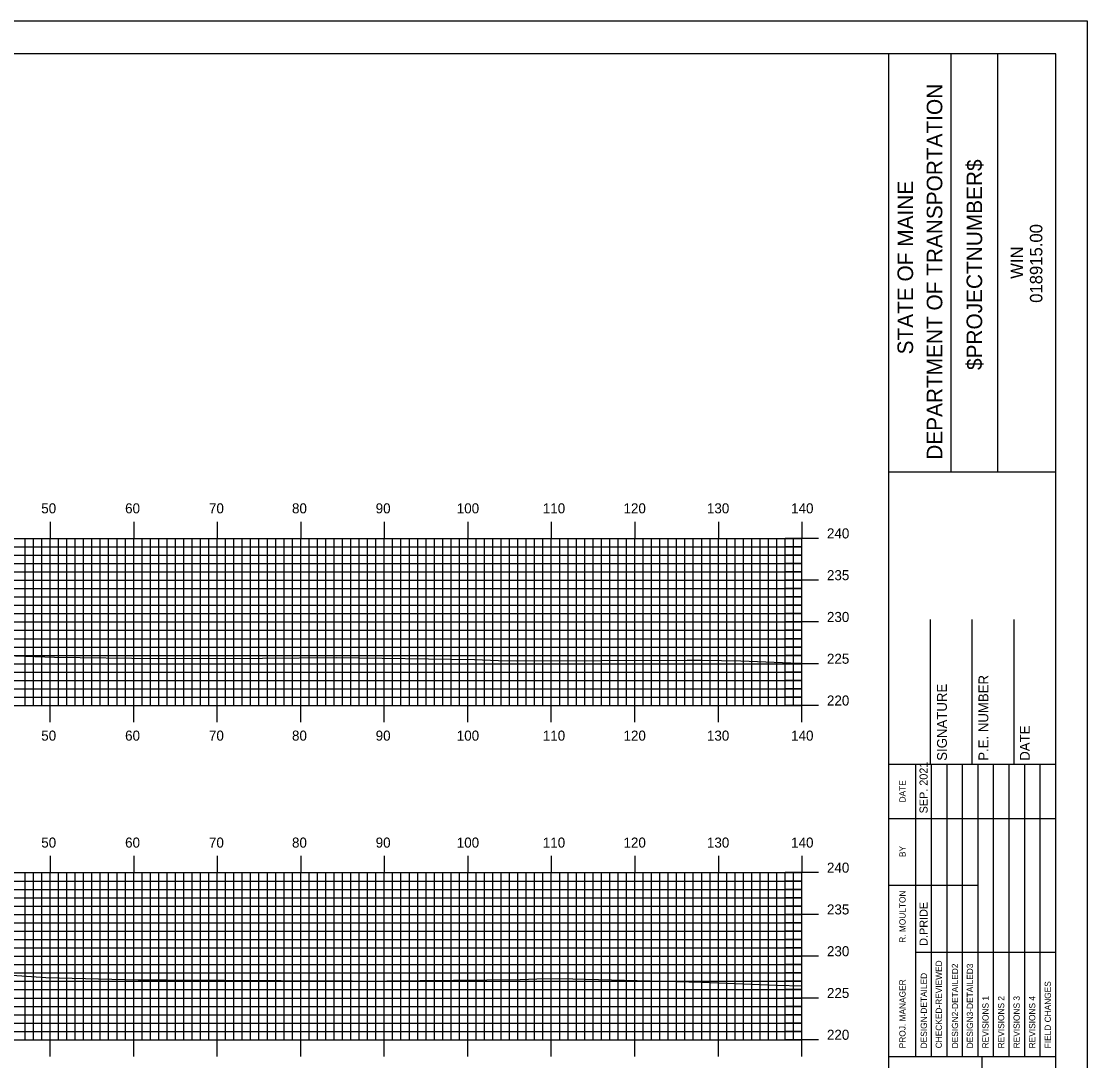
# Model space of a CAD drawing. Extents: x 1803503 to 1803847, y 442591 to 442811.
# Drawn here: x 1803715.7 to 1803843.4, y 442686.2 to 442810.5 of the extents above; entities that cross this region are included whole.
import ezdxf

# ---------------------------------------------------------------- set-up
doc = ezdxf.new("R2010")
doc.units = 0
for name, color, linetype in [('BORDER', 7, 'Continuous'), ('H_V ANNOTATION', 7, 'Continuous'), ('MAJOR', 7, 'Continuous'), ('MINOR', 7, 'Continuous'), ('PLOT BOUNDARY', 7, 'Continuous'), ('S_Roadway_Centerline', 7, 'Continuous')]:
    doc.layers.add(name, color=color, linetype=linetype)

msp = doc.modelspace()

# ---------------------------------------------------------------- linework, layer by layer
at = {"layer": 'BORDER'}
for p, q in [((1803819.54, 442596.67), (1803819.54, 442806.67)), ((1803827, 442756.66), (1803827, 442806.66)), ((1803832.59, 442756.66), (1803832.59, 442806.66)), ((1803819.54, 442756.65), (1803839.54, 442756.65)), ((1803824.54, 442721.67), (1803824.54, 442738.97)), ((1803829.54, 442721.67), (1803829.54, 442738.97)), ((1803834.54, 442721.67), (1803834.54, 442738.97)), ((1803819.54, 442721.67), (1803839.54, 442721.67)), ((1803819.54, 442686.67), (1803839.54, 442686.67)), ((1803830.72, 442616.67), (1803830.72, 442686.67))]:
    msp.add_line(p, q, dxfattribs=at)
msp.add_lwpolyline([(1803519.54, 442596.67), (1803839.54, 442596.67), (1803839.54, 442806.67), (1803519.54, 442806.67)], close=True, dxfattribs=at)
for points in [[(1803822.77, 442715.17), (1803822.77, 442721.67)], [(1803824.64, 442686.68), (1803824.64, 442721.67)], [(1803826.5, 442721.67), (1803826.5, 442686.68)], [(1803828.36, 442686.68), (1803828.36, 442721.67)], [(1803830.23, 442686.68), (1803830.23, 442721.67)], [(1803832.09, 442686.68), (1803832.09, 442721.67)], [(1803833.95, 442686.68), (1803833.95, 442721.67)], [(1803835.82, 442686.68), (1803835.82, 442721.67)], [(1803837.68, 442686.68), (1803837.68, 442721.67)], [(1803822.77, 442686.68), (1803822.77, 442720.26)], [(1803819.54, 442715.17), (1803839.54, 442715.17)], [(1803819.54, 442707.17), (1803822.77, 442707.17)], [(1803822.77, 442707.17), (1803830.22, 442707.17)], [(1803822.77, 442699.17), (1803839.54, 442699.17)]]:
    msp.add_lwpolyline(points, dxfattribs=at)
at = {"layer": 'MAJOR'}
for p, q in [((1803719.14, 442750.67), (1803719.14, 442748.67)), ((1803729.14, 442750.67), (1803729.14, 442748.67)), ((1803739.14, 442750.67), (1803739.14, 442748.67)), ((1803749.14, 442750.67), (1803749.14, 442748.67)), ((1803759.14, 442750.67), (1803759.14, 442748.67)), ((1803769.14, 442750.67), (1803769.14, 442748.67)), ((1803779.14, 442750.67), (1803779.14, 442748.67)), ((1803789.14, 442750.67), (1803789.14, 442748.67)), ((1803799.14, 442750.67), (1803799.14, 442748.67)), ((1803809.14, 442750.67), (1803809.14, 442748.67)), ((1803529.14, 442748.67), (1803809.14, 442748.67)), ((1803529.14, 442748.67), (1803809.14, 442748.67)), ((1803719.14, 442728.67), (1803719.14, 442748.67)), ((1803729.14, 442728.67), (1803729.14, 442748.67)), ((1803739.14, 442728.67), (1803739.14, 442748.67)), ((1803749.14, 442728.67), (1803749.14, 442748.67)), ((1803759.14, 442728.67), (1803759.14, 442748.67)), ((1803769.14, 442728.67), (1803769.14, 442748.67)), ((1803779.14, 442728.67), (1803779.14, 442748.67)), ((1803789.14, 442728.67), (1803789.14, 442748.67)), ((1803799.14, 442728.67), (1803799.14, 442748.67)), ((1803811.14, 442748.67), (1803807.14, 442748.67)), ((1803809.14, 442728.67), (1803809.14, 442748.67)), ((1803809.14, 442728.67), (1803809.14, 442748.67)), ((1803529.14, 442743.67), (1803809.14, 442743.67)), ((1803811.14, 442743.67), (1803807.14, 442743.67)), ((1803529.14, 442738.67), (1803809.14, 442738.67)), ((1803811.14, 442738.67), (1803807.14, 442738.67)), ((1803529.14, 442733.67), (1803809.14, 442733.67)), ((1803811.14, 442733.67), (1803807.14, 442733.67)), ((1803529.14, 442728.67), (1803809.14, 442728.67)), ((1803529.14, 442728.67), (1803809.14, 442728.67)), ((1803719.14, 442726.66), (1803719.14, 442728.67)), ((1803729.14, 442726.66), (1803729.14, 442728.67)), ((1803739.14, 442726.66), (1803739.14, 442728.67)), ((1803749.14, 442726.66), (1803749.14, 442728.67)), ((1803759.14, 442726.66), (1803759.14, 442728.67)), ((1803769.14, 442726.66), (1803769.14, 442728.67)), ((1803779.14, 442726.66), (1803779.14, 442728.67)), ((1803789.14, 442726.66), (1803789.14, 442728.67)), ((1803799.14, 442726.66), (1803799.14, 442728.67)), ((1803811.14, 442728.67), (1803807.14, 442728.67)), ((1803809.14, 442726.66), (1803809.14, 442728.67)), ((1803719.14, 442710.67), (1803719.14, 442708.67)), ((1803729.14, 442710.67), (1803729.14, 442708.67)), ((1803739.14, 442710.67), (1803739.14, 442708.67)), ((1803749.14, 442710.67), (1803749.14, 442708.67)), ((1803759.14, 442710.67), (1803759.14, 442708.67)), ((1803769.14, 442710.67), (1803769.14, 442708.67)), ((1803779.14, 442710.67), (1803779.14, 442708.67)), ((1803789.14, 442710.67), (1803789.14, 442708.67)), ((1803799.14, 442710.67), (1803799.14, 442708.67)), ((1803809.14, 442710.67), (1803809.14, 442708.67)), ((1803529.14, 442708.67), (1803809.14, 442708.67)), ((1803529.14, 442708.67), (1803809.14, 442708.67)), ((1803719.14, 442688.67), (1803719.14, 442708.67)), ((1803729.14, 442688.67), (1803729.14, 442708.67)), ((1803739.14, 442688.67), (1803739.14, 442708.67)), ((1803749.14, 442688.67), (1803749.14, 442708.67)), ((1803759.14, 442688.67), (1803759.14, 442708.67)), ((1803769.14, 442688.67), (1803769.14, 442708.67)), ((1803779.14, 442688.67), (1803779.14, 442708.67)), ((1803789.14, 442688.67), (1803789.14, 442708.67)), ((1803799.14, 442688.67), (1803799.14, 442708.67)), ((1803811.14, 442708.67), (1803807.14, 442708.67)), ((1803809.14, 442688.67), (1803809.14, 442708.67)), ((1803809.14, 442688.67), (1803809.14, 442708.67)), ((1803529.14, 442703.67), (1803809.14, 442703.67)), ((1803811.14, 442703.67), (1803807.14, 442703.67)), ((1803529.14, 442698.67), (1803809.14, 442698.67)), ((1803811.14, 442698.67), (1803807.14, 442698.67)), ((1803529.14, 442693.67), (1803809.14, 442693.67)), ((1803811.14, 442693.67), (1803807.14, 442693.67)), ((1803529.14, 442688.67), (1803809.14, 442688.67)), ((1803529.14, 442688.67), (1803809.14, 442688.67)), ((1803719.14, 442686.66), (1803719.14, 442688.67)), ((1803729.14, 442686.66), (1803729.14, 442688.67)), ((1803739.14, 442686.66), (1803739.14, 442688.67)), ((1803749.14, 442686.66), (1803749.14, 442688.67)), ((1803759.14, 442686.66), (1803759.14, 442688.67)), ((1803769.14, 442686.66), (1803769.14, 442688.67)), ((1803779.14, 442686.66), (1803779.14, 442688.67)), ((1803789.14, 442686.66), (1803789.14, 442688.67)), ((1803799.14, 442686.66), (1803799.14, 442688.67)), ((1803811.14, 442688.67), (1803807.14, 442688.67)), ((1803809.14, 442686.66), (1803809.14, 442688.67))]:
    msp.add_line(p, q, dxfattribs=at)
at = {"layer": 'MINOR'}
for p, q in [((1803716.14, 442728.67), (1803716.14, 442748.67)), ((1803717.14, 442728.67), (1803717.14, 442748.67)), ((1803718.14, 442728.67), (1803718.14, 442748.67)), ((1803720.14, 442728.67), (1803720.14, 442748.67)), ((1803721.14, 442728.67), (1803721.14, 442748.67)), ((1803722.14, 442728.67), (1803722.14, 442748.67)), ((1803723.14, 442728.67), (1803723.14, 442748.67)), ((1803724.14, 442728.67), (1803724.14, 442748.67)), ((1803725.14, 442728.67), (1803725.14, 442748.67)), ((1803726.14, 442728.67), (1803726.14, 442748.67)), ((1803727.14, 442728.67), (1803727.14, 442748.67)), ((1803728.14, 442728.67), (1803728.14, 442748.67)), ((1803730.14, 442728.67), (1803730.14, 442748.67)), ((1803731.14, 442728.67), (1803731.14, 442748.67)), ((1803732.14, 442728.67), (1803732.14, 442748.67)), ((1803733.14, 442728.67), (1803733.14, 442748.67)), ((1803734.14, 442728.67), (1803734.14, 442748.67)), ((1803735.14, 442728.67), (1803735.14, 442748.67)), ((1803736.14, 442728.67), (1803736.14, 442748.67)), ((1803737.14, 442728.67), (1803737.14, 442748.67)), ((1803738.14, 442728.67), (1803738.14, 442748.67)), ((1803740.14, 442728.67), (1803740.14, 442748.67)), ((1803741.14, 442728.67), (1803741.14, 442748.67)), ((1803742.14, 442728.67), (1803742.14, 442748.67)), ((1803743.14, 442728.67), (1803743.14, 442748.67)), ((1803744.14, 442728.67), (1803744.14, 442748.67)), ((1803745.14, 442728.67), (1803745.14, 442748.67)), ((1803746.14, 442728.67), (1803746.14, 442748.67)), ((1803747.14, 442728.67), (1803747.14, 442748.67)), ((1803748.14, 442728.67), (1803748.14, 442748.67)), ((1803750.14, 442728.67), (1803750.14, 442748.67)), ((1803751.14, 442728.67), (1803751.14, 442748.67)), ((1803752.14, 442728.67), (1803752.14, 442748.67)), ((1803753.14, 442728.67), (1803753.14, 442748.67)), ((1803754.14, 442728.67), (1803754.14, 442748.67)), ((1803755.14, 442728.67), (1803755.14, 442748.67)), ((1803756.14, 442728.67), (1803756.14, 442748.67)), ((1803757.14, 442728.67), (1803757.14, 442748.67)), ((1803758.14, 442728.67), (1803758.14, 442748.67)), ((1803760.14, 442728.67), (1803760.14, 442748.67)), ((1803761.14, 442728.67), (1803761.14, 442748.67)), ((1803762.14, 442728.67), (1803762.14, 442748.67)), ((1803763.14, 442728.67), (1803763.14, 442748.67)), ((1803764.14, 442728.67), (1803764.14, 442748.67)), ((1803765.14, 442728.67), (1803765.14, 442748.67)), ((1803766.14, 442728.67), (1803766.14, 442748.67)), ((1803767.14, 442728.67), (1803767.14, 442748.67)), ((1803768.14, 442728.67), (1803768.14, 442748.67)), ((1803770.14, 442728.67), (1803770.14, 442748.67)), ((1803771.14, 442728.67), (1803771.14, 442748.67)), ((1803772.14, 442728.67), (1803772.14, 442748.67)), ((1803773.14, 442728.67), (1803773.14, 442748.67)), ((1803774.14, 442728.67), (1803774.14, 442748.67)), ((1803775.14, 442728.67), (1803775.14, 442748.67)), ((1803776.14, 442728.67), (1803776.14, 442748.67)), ((1803777.14, 442728.67), (1803777.14, 442748.67)), ((1803778.14, 442728.67), (1803778.14, 442748.67)), ((1803780.14, 442728.67), (1803780.14, 442748.67)), ((1803781.14, 442728.67), (1803781.14, 442748.67)), ((1803782.14, 442728.67), (1803782.14, 442748.67)), ((1803783.14, 442728.67), (1803783.14, 442748.67)), ((1803784.14, 442728.67), (1803784.14, 442748.67)), ((1803785.14, 442728.67), (1803785.14, 442748.67)), ((1803786.14, 442728.67), (1803786.14, 442748.67)), ((1803787.14, 442728.67), (1803787.14, 442748.67)), ((1803788.14, 442728.67), (1803788.14, 442748.67)), ((1803790.14, 442728.67), (1803790.14, 442748.67)), ((1803791.14, 442728.67), (1803791.14, 442748.67)), ((1803792.14, 442728.67), (1803792.14, 442748.67)), ((1803793.14, 442728.67), (1803793.14, 442748.67)), ((1803794.14, 442728.67), (1803794.14, 442748.67)), ((1803795.14, 442728.67), (1803795.14, 442748.67)), ((1803796.14, 442728.67), (1803796.14, 442748.67)), ((1803797.14, 442728.67), (1803797.14, 442748.67)), ((1803798.14, 442728.67), (1803798.14, 442748.67)), ((1803800.14, 442728.67), (1803800.14, 442748.67)), ((1803801.14, 442728.67), (1803801.14, 442748.67)), ((1803802.14, 442728.67), (1803802.14, 442748.67)), ((1803803.14, 442728.67), (1803803.14, 442748.67)), ((1803804.14, 442728.67), (1803804.14, 442748.67)), ((1803805.14, 442728.67), (1803805.14, 442748.67)), ((1803806.14, 442728.67), (1803806.14, 442748.67)), ((1803807.14, 442728.67), (1803807.14, 442748.67)), ((1803808.14, 442728.67), (1803808.14, 442748.67)), ((1803529.14, 442747.67), (1803809.14, 442747.67)), ((1803809.14, 442747.67), (1803807.14, 442747.67)), ((1803529.14, 442746.67), (1803809.14, 442746.67)), ((1803809.14, 442746.67), (1803807.14, 442746.67)), ((1803529.14, 442745.67), (1803809.14, 442745.67)), ((1803809.14, 442745.67), (1803807.14, 442745.67)), ((1803529.14, 442744.67), (1803809.14, 442744.67)), ((1803809.14, 442744.67), (1803807.14, 442744.67)), ((1803529.14, 442742.67), (1803809.14, 442742.67)), ((1803809.14, 442742.67), (1803807.14, 442742.67)), ((1803529.14, 442741.67), (1803809.14, 442741.67)), ((1803809.14, 442741.67), (1803807.14, 442741.67)), ((1803529.14, 442740.67), (1803809.14, 442740.67)), ((1803529.14, 442739.67), (1803809.14, 442739.67)), ((1803809.14, 442740.67), (1803807.14, 442740.67)), ((1803809.14, 442739.67), (1803807.14, 442739.67)), ((1803529.14, 442737.67), (1803809.14, 442737.67)), ((1803809.14, 442737.67), (1803807.14, 442737.67)), ((1803529.14, 442736.67), (1803809.14, 442736.67)), ((1803809.14, 442736.67), (1803807.14, 442736.67)), ((1803529.14, 442735.67), (1803809.14, 442735.67)), ((1803529.14, 442734.67), (1803809.14, 442734.67)), ((1803809.14, 442735.67), (1803807.14, 442735.67)), ((1803809.14, 442734.67), (1803807.14, 442734.67)), ((1803529.14, 442732.67), (1803809.14, 442732.67)), ((1803809.14, 442732.67), (1803807.14, 442732.67)), ((1803529.14, 442731.67), (1803809.14, 442731.67)), ((1803809.14, 442731.67), (1803807.14, 442731.67)), ((1803529.14, 442730.67), (1803809.14, 442730.67)), ((1803529.14, 442729.67), (1803809.14, 442729.67)), ((1803809.14, 442730.67), (1803807.14, 442730.67)), ((1803809.14, 442729.67), (1803807.14, 442729.67)), ((1803716.14, 442688.67), (1803716.14, 442708.67)), ((1803717.14, 442688.67), (1803717.14, 442708.67)), ((1803718.14, 442688.67), (1803718.14, 442708.67)), ((1803720.14, 442688.67), (1803720.14, 442708.67)), ((1803721.14, 442688.67), (1803721.14, 442708.67)), ((1803722.14, 442688.67), (1803722.14, 442708.67)), ((1803723.14, 442688.67), (1803723.14, 442708.67)), ((1803724.14, 442688.67), (1803724.14, 442708.67)), ((1803725.14, 442688.67), (1803725.14, 442708.67)), ((1803726.14, 442688.67), (1803726.14, 442708.67)), ((1803727.14, 442688.67), (1803727.14, 442708.67)), ((1803728.14, 442688.67), (1803728.14, 442708.67)), ((1803730.14, 442688.67), (1803730.14, 442708.67)), ((1803731.14, 442688.67), (1803731.14, 442708.67)), ((1803732.14, 442688.67), (1803732.14, 442708.67)), ((1803733.14, 442688.67), (1803733.14, 442708.67)), ((1803734.14, 442688.67), (1803734.14, 442708.67)), ((1803735.14, 442688.67), (1803735.14, 442708.67)), ((1803736.14, 442688.67), (1803736.14, 442708.67)), ((1803737.14, 442688.67), (1803737.14, 442708.67)), ((1803738.14, 442688.67), (1803738.14, 442708.67)), ((1803740.14, 442688.67), (1803740.14, 442708.67)), ((1803741.14, 442688.67), (1803741.14, 442708.67)), ((1803742.14, 442688.67), (1803742.14, 442708.67)), ((1803743.14, 442688.67), (1803743.14, 442708.67)), ((1803744.14, 442688.67), (1803744.14, 442708.67)), ((1803745.14, 442688.67), (1803745.14, 442708.67)), ((1803746.14, 442688.67), (1803746.14, 442708.67)), ((1803747.14, 442688.67), (1803747.14, 442708.67)), ((1803748.14, 442688.67), (1803748.14, 442708.67)), ((1803750.14, 442688.67), (1803750.14, 442708.67)), ((1803751.14, 442688.67), (1803751.14, 442708.67)), ((1803752.14, 442688.67), (1803752.14, 442708.67)), ((1803753.14, 442688.67), (1803753.14, 442708.67)), ((1803754.14, 442688.67), (1803754.14, 442708.67)), ((1803755.14, 442688.67), (1803755.14, 442708.67)), ((1803756.14, 442688.67), (1803756.14, 442708.67)), ((1803757.14, 442688.67), (1803757.14, 442708.67)), ((1803758.14, 442688.67), (1803758.14, 442708.67)), ((1803760.14, 442688.67), (1803760.14, 442708.67)), ((1803761.14, 442688.67), (1803761.14, 442708.67)), ((1803762.14, 442688.67), (1803762.14, 442708.67)), ((1803763.14, 442688.67), (1803763.14, 442708.67)), ((1803764.14, 442688.67), (1803764.14, 442708.67)), ((1803765.14, 442688.67), (1803765.14, 442708.67)), ((1803766.14, 442688.67), (1803766.14, 442708.67)), ((1803767.14, 442688.67), (1803767.14, 442708.67)), ((1803768.14, 442688.67), (1803768.14, 442708.67)), ((1803770.14, 442688.67), (1803770.14, 442708.67)), ((1803771.14, 442688.67), (1803771.14, 442708.67)), ((1803772.14, 442688.67), (1803772.14, 442708.67)), ((1803773.14, 442688.67), (1803773.14, 442708.67)), ((1803774.14, 442688.67), (1803774.14, 442708.67)), ((1803775.14, 442688.67), (1803775.14, 442708.67)), ((1803776.14, 442688.67), (1803776.14, 442708.67)), ((1803777.14, 442688.67), (1803777.14, 442708.67)), ((1803778.14, 442688.67), (1803778.14, 442708.67)), ((1803780.14, 442688.67), (1803780.14, 442708.67)), ((1803781.14, 442688.67), (1803781.14, 442708.67)), ((1803782.14, 442688.67), (1803782.14, 442708.67)), ((1803783.14, 442688.67), (1803783.14, 442708.67)), ((1803784.14, 442688.67), (1803784.14, 442708.67)), ((1803785.14, 442688.67), (1803785.14, 442708.67)), ((1803786.14, 442688.67), (1803786.14, 442708.67)), ((1803787.14, 442688.67), (1803787.14, 442708.67)), ((1803788.14, 442688.67), (1803788.14, 442708.67)), ((1803790.14, 442688.67), (1803790.14, 442708.67)), ((1803791.14, 442688.67), (1803791.14, 442708.67)), ((1803792.14, 442688.67), (1803792.14, 442708.67)), ((1803793.14, 442688.67), (1803793.14, 442708.67)), ((1803794.14, 442688.67), (1803794.14, 442708.67)), ((1803795.14, 442688.67), (1803795.14, 442708.67)), ((1803796.14, 442688.67), (1803796.14, 442708.67)), ((1803797.14, 442688.67), (1803797.14, 442708.67)), ((1803798.14, 442688.67), (1803798.14, 442708.67)), ((1803800.14, 442688.67), (1803800.14, 442708.67)), ((1803801.14, 442688.67), (1803801.14, 442708.67)), ((1803802.14, 442688.67), (1803802.14, 442708.67)), ((1803803.14, 442688.67), (1803803.14, 442708.67)), ((1803804.14, 442688.67), (1803804.14, 442708.67)), ((1803805.14, 442688.67), (1803805.14, 442708.67)), ((1803806.14, 442688.67), (1803806.14, 442708.67)), ((1803807.14, 442688.67), (1803807.14, 442708.67)), ((1803808.14, 442688.67), (1803808.14, 442708.67)), ((1803529.14, 442707.67), (1803809.14, 442707.67)), ((1803529.14, 442706.67), (1803809.14, 442706.67)), ((1803809.14, 442707.67), (1803807.14, 442707.67)), ((1803809.14, 442706.67), (1803807.14, 442706.67)), ((1803529.14, 442705.67), (1803809.14, 442705.67)), ((1803809.14, 442705.67), (1803807.14, 442705.67)), ((1803529.14, 442704.67), (1803809.14, 442704.67)), ((1803809.14, 442704.67), (1803807.14, 442704.67)), ((1803529.14, 442702.67), (1803809.14, 442702.67)), ((1803809.14, 442702.67), (1803807.14, 442702.67)), ((1803529.14, 442701.67), (1803809.14, 442701.67)), ((1803809.14, 442701.67), (1803807.14, 442701.67)), ((1803529.14, 442700.67), (1803809.14, 442700.67)), ((1803809.14, 442700.67), (1803807.14, 442700.67)), ((1803529.14, 442699.67), (1803809.14, 442699.67)), ((1803809.14, 442699.67), (1803807.14, 442699.67)), ((1803529.14, 442697.67), (1803809.14, 442697.67)), ((1803809.14, 442697.67), (1803807.14, 442697.67)), ((1803529.14, 442696.67), (1803809.14, 442696.67)), ((1803809.14, 442696.67), (1803807.14, 442696.67)), ((1803529.14, 442695.67), (1803809.14, 442695.67)), ((1803809.14, 442695.67), (1803807.14, 442695.67)), ((1803529.14, 442694.67), (1803809.14, 442694.67)), ((1803809.14, 442694.67), (1803807.14, 442694.67)), ((1803529.14, 442692.67), (1803809.14, 442692.67)), ((1803809.14, 442692.67), (1803807.14, 442692.67)), ((1803529.14, 442691.67), (1803809.14, 442691.67)), ((1803809.14, 442691.67), (1803807.14, 442691.67)), ((1803529.14, 442690.67), (1803809.14, 442690.67)), ((1803809.14, 442690.67), (1803807.14, 442690.67)), ((1803529.14, 442689.67), (1803809.14, 442689.67)), ((1803809.14, 442689.67), (1803807.14, 442689.67))]:
    msp.add_line(p, q, dxfattribs=at)
at = {"layer": 'PLOT BOUNDARY'}
msp.add_lwpolyline([(1803503.35, 442590.55), (1803843.35, 442590.55), (1803843.35, 442810.55), (1803503.35, 442810.55)], close=True, dxfattribs=at)
at = {"layer": 'S_Roadway_Centerline'}
for points in [[(1803711.43, 442734.73), (1803719.65, 442734.44), (1803731.98, 442734.31), (1803744.55, 442734.34), (1803753.37, 442734.43), (1803769.95, 442734.16), (1803772.83, 442734.04), (1803774.94, 442734.02), (1803795.41, 442734.11), (1803797.18, 442734.08), (1803801.84, 442734.02), (1803807.82, 442733.77), (1803809.06, 442733.73), (1803809.14, 442733.73), (1803809.14, 442733.73)], [(1803710.51, 442696.69), (1803718.61, 442696.12), (1803729.69, 442695.86), (1803731.65, 442695.84), (1803733.12, 442695.86), (1803753.66, 442695.71), (1803755.17, 442695.71), (1803755.31, 442695.71), (1803755.44, 442695.7), (1803775.4, 442695.9), (1803777.41, 442695.96), (1803780.17, 442696), (1803797.17, 442695.56), (1803806.14, 442695.2), (1803809.14, 442695.13)]]:
    msp.add_lwpolyline(points, dxfattribs=at)

# ---------------------------------------------------------------- texts
at = {"layer": 'BORDER'}
for s, height, p in [('DEPARTMENT OF TRANSPORTATION', 1.8635, (1803825.95, 442758.08)), ('$PROJECTNUMBER$', 1.8635, (1803830.72, 442768.82)), ('STATE OF MAINE', 1.8635, (1803822.45, 442770.69)), ('018915.00', 1.491, (1803837.93, 442776.86)), ('WIN', 1.491, (1803835.61, 442779.73)), ('P.E. NUMBER', 1.1811, (1803831.46, 442722.06)), ('SIGNATURE', 1.181, (1803826.5, 442722.06)), ('DATE', 1.181, (1803836.42, 442722.06)), ('SEP. 2021', 0.969, (1803824.19, 442715.76)), ('DATE', 0.743, (1803821.55, 442717.08)), ('BY', 0.743, (1803821.55, 442710.54)), ('R. MOULTON', 0.745, (1803821.55, 442700.28)), ('D.PRIDE', 0.969, (1803824.19, 442699.92)), ('CHECKED-REVIEWED', 0.7455, (1803825.9, 442687.65)), ('DESIGN2-DETAILED2', 0.7455, (1803827.84, 442687.65)), ('DESIGN3-DETAILED3', 0.7455, (1803829.63, 442687.65)), ('DESIGN-DETAILED', 0.7455, (1803824.11, 442687.65)), ('PROJ. MANAGER', 0.7455, (1803821.55, 442687.65)), ('FIELD CHANGES', 0.7455, (1803838.95, 442687.65)), ('REVISIONS 1', 0.7455, (1803831.49, 442687.65)), ('REVISIONS 2', 0.7455, (1803833.36, 442687.65)), ('REVISIONS 3', 0.7455, (1803835.22, 442687.65)), ('REVISIONS 4', 0.7455, (1803837.08, 442687.65))]:
    msp.add_text(s, height=height, rotation=90, dxfattribs=at).set_placement(p)
at = {"layer": 'H_V ANNOTATION'}
for s, p in [('50', (1803718.07, 442751.67)), ('60', (1803728.11, 442751.67)), ('70', (1803738.15, 442751.67)), ('80', (1803748.09, 442751.67)), ('90', (1803758.11, 442751.67)), ('100', (1803767.82, 442751.67)), ('110', (1803778.12, 442751.67)), ('120', (1803787.78, 442751.67)), ('130', (1803797.77, 442751.67)), ('140', (1803807.85, 442751.67)), ('240', (1803812.14, 442748.67)), ('235', (1803812.14, 442743.67)), ('230', (1803812.14, 442738.67)), ('225', (1803812.14, 442733.67)), ('220', (1803812.14, 442728.67)), ('50', (1803718.07, 442724.47)), ('60', (1803728.11, 442724.47)), ('70', (1803738.15, 442724.47)), ('80', (1803748.09, 442724.47)), ('90', (1803758.11, 442724.47)), ('100', (1803767.82, 442724.47)), ('110', (1803778.12, 442724.47)), ('120', (1803787.78, 442724.47)), ('130', (1803797.77, 442724.47)), ('140', (1803807.85, 442724.47)), ('50', (1803718.07, 442711.67)), ('60', (1803728.11, 442711.67)), ('70', (1803738.15, 442711.67)), ('80', (1803748.09, 442711.67)), ('90', (1803758.11, 442711.67)), ('100', (1803767.82, 442711.67)), ('110', (1803778.12, 442711.67)), ('120', (1803787.78, 442711.67)), ('130', (1803797.77, 442711.67)), ('140', (1803807.85, 442711.67)), ('240', (1803812.14, 442708.67)), ('235', (1803812.14, 442703.67)), ('230', (1803812.14, 442698.67)), ('225', (1803812.14, 442693.67)), ('220', (1803812.14, 442688.67))]:
    msp.add_text(s, height=1.2, dxfattribs=at).set_placement(p)

doc.saveas('drawing.dxf')
